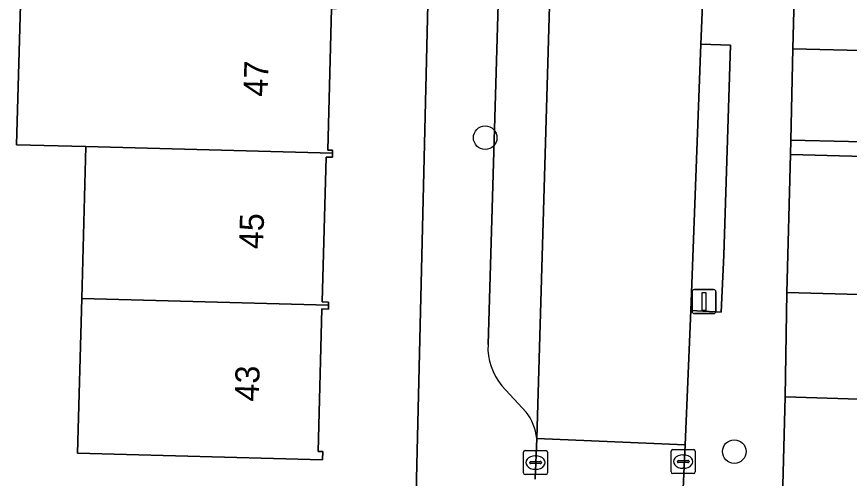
# Model space of a CAD drawing. Extents: x 162082 to 163401, y 388089 to 388636.
# Drawn here: x 162508.73 to 162543.27, y 388329.44 to 388348.59 of the extents above; entities that cross this region are included whole.
import ezdxf

# ---------------------------------------------------------------- set-up
doc = ezdxf.new("R2010")
doc.units = 0
for name, color, linetype in [('IMGEO_Boom', 7, 'Continuous'), ('IMGEO_Erf', 7, 'Continuous'), ('IMGEO_Kolk', 7, 'Continuous'), ('IMGEO_Lichtmast', 7, 'Continuous'), ('IMGEO_Pand', 7, 'Continuous'), ('IMGEO_Pand_nummerreeks', 7, 'Continuous'), ('IMGEO_Parkeervlak_open', 7, 'Continuous'), ('IMGEO_Rijbaan_lokaal_open', 7, 'Continuous'), ('IMGEO_Voetpad_open', 7, 'Continuous')]:
    doc.layers.add(name, color=color, linetype=linetype)

msp = doc.modelspace()

# ---------------------------------------------------------------- linework, layer by layer
at = {"layer": 'IMGEO_Boom'}
for centre in [(162528.169, 388343.568), (162538.502, 388330.551)]:
    msp.add_circle(centre, 0.489, dxfattribs=at)
at = {"layer": 'IMGEO_Erf'}
for points in [[(162525.301, 388328.836), (162526.307, 388370.528), (162527.255, 388399.633)], [(162541.4, 388365.284), (162540.932, 388347.25), (162550.503, 388347.02)], [(162521.795, 388348.932), (162521.635, 388343.056), (162521.841, 388343.05), (162521.837, 388342.922), (162521.833, 388342.76), (162521.575, 388342.767), (162521.412, 388336.756), (162521.673, 388336.749), (162521.67, 388336.623), (162521.665, 388336.459), (162521.397, 388336.466), (162521.236, 388330.554), (162521.437, 388330.548), (162521.427, 388330.205), (162511.261, 388330.482), (162511.435, 388336.901), (162511.607, 388343.199), (162508.734, 388343.277), (162508.905, 388349.574)]]:
    msp.add_lwpolyline(points, dxfattribs=at)
at = {"layer": 'IMGEO_Kolk'}
for p, q in [((162535.955, 388330.637), (162536.807, 388330.637)), ((162529.755, 388329.671), (162529.755, 388330.523)), ((162529.83, 388330.597), (162530.682, 388330.597)), ((162530.243, 388330.377), (162530.268, 388330.377)), ((162530.756, 388330.523), (162530.756, 388329.671)), ((162535.88, 388329.711), (162535.88, 388330.563)), ((162536.368, 388330.417), (162536.393, 388330.417)), ((162536.881, 388330.563), (162536.881, 388329.711)), ((162530.014, 388330.091), (162530.014, 388330.103)), ((162530.452, 388330.054), (162530.054, 388330.054)), ((162530.057, 388330.14), (162530.455, 388330.14)), ((162530.498, 388330.103), (162530.498, 388330.091)), ((162536.139, 388330.131), (162536.139, 388330.143)), ((162536.577, 388330.094), (162536.179, 388330.094)), ((162536.182, 388330.18), (162536.58, 388330.18)), ((162536.623, 388330.143), (162536.623, 388330.131)), ((162530.682, 388329.597), (162529.83, 388329.597)), ((162530.266, 388329.817), (162530.241, 388329.817)), ((162536.807, 388329.637), (162535.955, 388329.637)), ((162536.391, 388329.857), (162536.366, 388329.857))]:
    msp.add_line(p, q, dxfattribs=at)
for points in [[(162535.955, 388330.637), (162536.807, 388330.637)], [(162529.755, 388329.671), (162529.755, 388330.523)], [(162529.83, 388330.597), (162530.682, 388330.597)], [(162530.756, 388330.523), (162530.756, 388329.671)], [(162535.88, 388329.711), (162535.88, 388330.563)], [(162536.881, 388330.563), (162536.881, 388329.711)], [(162530.682, 388329.597), (162529.83, 388329.597)], [(162536.807, 388329.637), (162535.955, 388329.637)]]:
    msp.add_lwpolyline(points, dxfattribs=at)
for centre, radius, start, end in [((162535.957, 388330.561), 0.0765, 91.552, 178.448), ((162535.957, 388330.561), 0.0765, 91.552, 178.448), ((162536.805, 388330.561), 0.0765, 1.552, 88.448), ((162536.805, 388330.561), 0.0765, 1.552, 88.448), ((162529.832, 388330.521), 0.0765, 91.552, 178.448), ((162529.832, 388330.521), 0.0765, 91.552, 178.448), ((162530.68, 388330.521), 0.0765, 1.552, 88.448), ((162530.68, 388330.521), 0.0765, 1.552, 88.448), ((162530.054, 388330.1), 0.0403, 85.8775, 175.7526), ((162530.051, 388330.09), 0.0366, 178.938, 274.7102), ((162530.455, 388330.097), 0.043, 264.8664, 352.4533), ((162530.459, 388330.102), 0.0386, 1.7309, 96.639), ((162536.179, 388330.14), 0.0403, 85.8775, 175.7526), ((162536.176, 388330.13), 0.0366, 178.938, 274.7102), ((162536.58, 388330.137), 0.043, 264.8664, 352.4533), ((162536.584, 388330.142), 0.0386, 1.7309, 96.639), ((162529.832, 388329.673), 0.0765, 181.552, 268.448), ((162529.832, 388329.673), 0.0765, 181.552, 268.448), ((162530.68, 388329.673), 0.0765, 271.552, 358.448), ((162530.68, 388329.673), 0.0765, 271.552, 358.448), ((162535.957, 388329.713), 0.0765, 181.552, 268.448), ((162535.957, 388329.713), 0.0765, 181.552, 268.448), ((162536.805, 388329.713), 0.0765, 271.552, 358.448), ((162536.805, 388329.713), 0.0765, 271.552, 358.448)]:
    msp.add_arc(centre, radius, start, end, dxfattribs=at)
for centre, major_axis, ratio, start_param, end_param in [((162530.242, 388330.097), (-0.387, 0.002), 0.722429, 4.712389, 7.853982), ((162530.267, 388330.097), (-0.39, 0.002), 0.717154, 1.570796, 4.712389), ((162536.367, 388330.137), (-0.387, 0.002), 0.722429, 4.712389, 7.853982), ((162536.392, 388330.137), (-0.39, 0.002), 0.717154, 1.570796, 4.712389)]:
    msp.add_ellipse(centre, major_axis=major_axis, ratio=ratio, start_param=start_param, end_param=end_param, dxfattribs=at)
at = {"layer": 'IMGEO_Lichtmast'}
for p, q in [((162536.85, 388337.274), (162537.64, 388337.274)), ((162537.64, 388337.274), (162536.85, 388337.274)), ((162536.75, 388336.374), (162536.75, 388337.174)), ((162536.75, 388337.174), (162536.75, 388336.374)), ((162537.74, 388337.174), (162537.74, 388336.374)), ((162537.74, 388336.374), (162537.74, 388337.174)), ((162537.64, 388336.274), (162536.85, 388336.274)), ((162536.85, 388336.274), (162537.64, 388336.274))]:
    msp.add_line(p, q, dxfattribs=at)
msp.add_lwpolyline([(162537.17, 388337.149), (162537.32, 388337.149), (162537.32, 388336.399), (162537.17, 388336.399), (162537.17, 388337.149)], dxfattribs=at)
for centre, start, end in [((162536.85, 388337.174), 90, 180), ((162536.85, 388337.174), 90, 180), ((162537.64, 388337.174), 0, 90), ((162537.64, 388337.174), 360, 90), ((162536.85, 388336.374), 180, 270), ((162536.85, 388336.374), 180, 270), ((162537.64, 388336.374), 270, 0), ((162537.64, 388336.374), 270, 0)]:
    msp.add_arc(centre, 0.1, start, end, dxfattribs=at)
at = {"layer": 'IMGEO_Pand'}
for points in [[(162521.795, 388348.932), (162522.006, 388348.926), (162522.014, 388349.218), (162511.778, 388349.496), (162508.905, 388349.574), (162508.734, 388343.277), (162511.607, 388343.199), (162521.837, 388342.922), (162521.841, 388343.05), (162521.635, 388343.056)], [(162550.412, 388343.243), (162550.503, 388347.02), (162540.932, 388347.25), (162540.842, 388343.472)], [(162521.837, 388342.922), (162511.607, 388343.199), (162511.435, 388336.901), (162521.67, 388336.623), (162521.673, 388336.749), (162521.412, 388336.756), (162521.575, 388342.767), (162521.833, 388342.76)], [(162521.67, 388336.623), (162511.435, 388336.901), (162511.261, 388330.482), (162521.427, 388330.205), (162521.437, 388330.548), (162521.236, 388330.554), (162521.397, 388336.466), (162521.665, 388336.459)]]:
    msp.add_lwpolyline(points, close=True, dxfattribs=at)
at = {"layer": 'IMGEO_Parkeervlak_open'}
for points in [[(162530.304, 388331.1), (162531.342, 388366.506), (162529.225, 388366.53), (162528.285, 388334.986)], [(162528.855, 388333.28), (162529.867, 388332.192)]]:
    msp.add_lwpolyline(points, dxfattribs=at)
msp.add_lwpolyline([(162568.065, 388331.956), (162568.161, 388336.385), (162540.683, 388337.145), (162540.608, 388332.828)], close=True, dxfattribs=at)
for centre, radius, start, end in [((162530.766, 388334.867), 2.484, 177.2457, 219.7048), ((162528.201, 388330.892), 2.113, 5.6541, 37.9668)]:
    msp.add_arc(centre, radius, start, end, dxfattribs=at)
at = {"layer": 'IMGEO_Rijbaan_lokaal_open'}
for points in [[(162537.119, 388347.448), (162537.181, 388349.095), (162537.563, 388363.414), (162537.661, 388366.432), (162531.342, 388366.506), (162530.304, 388331.1), (162536.46, 388330.832), (162536.703, 388336.4)], [(162573.176, 388315.745), (162573.857, 388341.976), (162540.827, 388342.868), (162540.683, 388337.145), (162568.161, 388336.385), (162568.065, 388331.956), (162567.804, 388322.464), (162567.649, 388316.822), (162567.624, 388315.895)]]:
    msp.add_lwpolyline(points, close=True, dxfattribs=at)
msp.add_lwpolyline([(162536.276, 388326.605), (162536.46, 388330.832), (162530.304, 388331.1), (162530.237, 388329.412)], dxfattribs=at)
at = {"layer": 'IMGEO_Voetpad_open'}
for points in [[(162533.992, 388452.596), (162533.998, 388454.185), (162528.815, 388454.241), (162527.34, 388403.481), (162527.255, 388399.633), (162526.307, 388370.528), (162525.301, 388328.836), (162525.177, 388324.075)], [(162528.285, 388334.986), (162529.225, 388366.53), (162529.569, 388378.1), (162530.137, 388396.475)], [(162540.608, 388332.828), (162540.683, 388337.145), (162540.827, 388342.868), (162540.842, 388343.472), (162540.932, 388347.25), (162541.4, 388365.284), (162541.427, 388370.401), (162540.815, 388370.404)], [(162537.181, 388349.095), (162537.119, 388347.448), (162538.343, 388347.409), (162538.069, 388338.696), (162537.955, 388336.339), (162536.703, 388336.4), (162536.46, 388330.832), (162536.276, 388326.605)], [(162529.867, 388332.192), (162528.855, 388333.28)], [(162527.208, 388317.995), (162530.329, 388312.664), (162533.867, 388312.548), (162536.13, 388312.489), (162540.075, 388312.386), (162540.608, 388332.828)], [(162530.237, 388329.412), (162530.304, 388331.1)]]:
    msp.add_lwpolyline(points, dxfattribs=at)
for points in [[(162537.955, 388336.339), (162538.069, 388338.696), (162538.343, 388347.409), (162537.119, 388347.448), (162536.703, 388336.4)], [(162554.162, 388343.153), (162550.412, 388343.243), (162540.842, 388343.472), (162540.827, 388342.868), (162573.857, 388341.976), (162573.176, 388315.745), (162573.98, 388315.724), (162573.986, 388315.885), (162574.093, 388319.684), (162574.154, 388322.28), (162574.26, 388326.045), (162574.328, 388328.531), (162574.434, 388332.27), (162574.483, 388334.837), (162574.589, 388338.583), (162574.679, 388342.663), (162573.141, 388342.682), (162569.381, 388342.775), (162566.88, 388342.86), (162563.037, 388342.956), (162560.478, 388342.951), (162556.732, 388343.045)], [(162566.815, 388322.494), (162567.804, 388322.464), (162568.065, 388331.956), (162540.608, 388332.828), (162540.075, 388312.386), (162568.204, 388311.652), (162568.242, 388311.654), (162573.835, 388311.494), (162573.888, 388313.371), (162573.98, 388315.724), (162573.176, 388315.745), (162567.624, 388315.895), (162567.649, 388316.822), (162566.646, 388316.859)]]:
    msp.add_lwpolyline(points, close=True, dxfattribs=at)
for centre, radius, start, end in [((162530.766, 388334.867), 2.484, 177.2457, 219.7048), ((162528.201, 388330.892), 2.113, 5.6541, 37.9668)]:
    msp.add_arc(centre, radius, start, end, dxfattribs=at)

# ---------------------------------------------------------------- texts
at = {"layer": 'IMGEO_Pand_nummerreeks'}
for s, rotation, p in [('47', 88.3558, (162519.138, 388345.258)), ('45', 88.3531, (162518.956, 388338.937)), ('43', 88.3531, (162518.774, 388332.617))]:
    msp.add_text(s, height=1, rotation=rotation, dxfattribs=at).set_placement(p)

doc.saveas('drawing.dxf')
